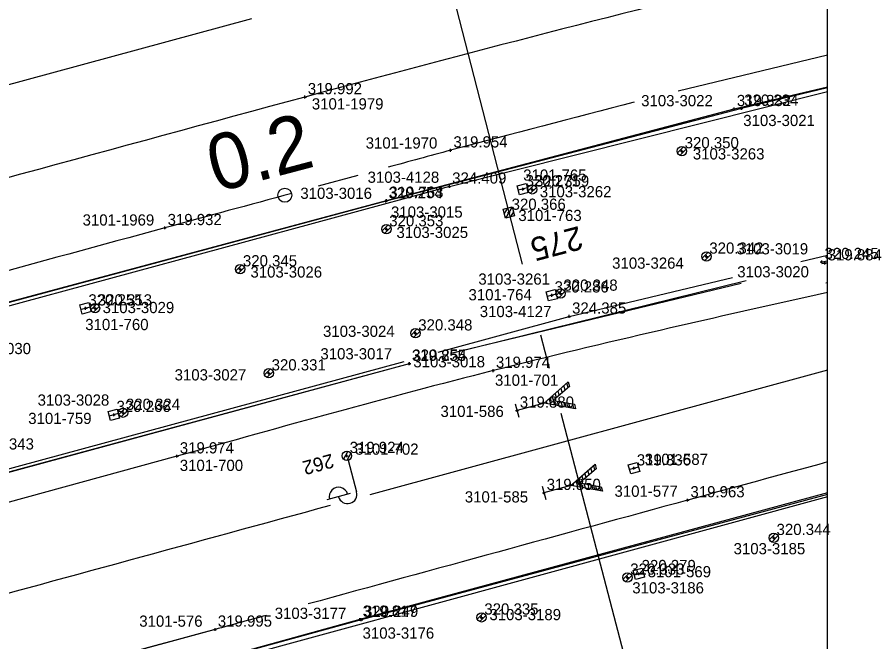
# Model space of a CAD drawing. Extents: x -821875 to -821475, y -1070280 to -1069975.
# Drawn here: x -821543.41 to -821497.95, y -1070194.92 to -1070161.48 of the extents above; entities that cross this region are included whole.
import ezdxf

# ---------------------------------------------------------------- set-up
doc = ezdxf.new("R2010")
doc.units = 0
for name, color, linetype in [('Vrstva 1', 7, 'Continuous'), ('Vrstva 11', 7, 'Continuous'), ('Vrstva 14', 7, 'Continuous'), ('Vrstva 25', 7, 'Continuous'), ('Vrstva 3', 7, 'Continuous'), ('Vrstva 36', 7, 'Continuous'), ('Vrstva 43', 7, 'Continuous'), ('Vrstva 6', 7, 'Continuous'), ('Vrstva 60', 7, 'Continuous'), ('Vrstva 61', 7, 'Continuous'), ('Vrstva 7', 7, 'Continuous')]:
    doc.layers.add(name, color=color, linetype=linetype)

# ---------------------------------------------------------------- blocks, each defined once
blk = doc.blocks.new('BOD')
at = {"layer": 'Vrstva 3'}
for p, q in [((-0.15, 0), (0.15, 0)), ((0, -0.15), (0, 0.15))]:
    blk.add_line(p, q, dxfattribs=at)

msp = doc.modelspace()

# ---------------------------------------------------------------- linework, layer by layer
at = {"layer": 'Vrstva 1'}
for p, q in [((-821530.858, -1070161.578), (-821554.553, -1070168.036)), ((-821500, -1070163.52), (-821508.002, -1070165.461)), ((-821525.155, -1070169.973), (-821527.289, -1070170.553)), ((-821500, -1070180.408), (-821524.524, -1070187.082)), ((-821532.805, -1070194.296), (-821551.797, -1070199.466))]:
    msp.add_line(p, q, dxfattribs=at)
msp.add_lwpolyline([(-821500, -1070000), (-821850, -1070000), (-821850, -1070250), (-821500, -1070250)], close=True, dxfattribs=at)
msp.add_lwpolyline([(-821500, -1070000), (-821850, -1070000), (-821850, -1070250), (-821500, -1070250)], close=True, dxfattribs=at)
msp.add_lwpolyline([(-821534.842, -1070185.015), (-821544.956, -1070187.779)], dxfattribs=at)
for points in [[(-821515.135, -1070116.801), (-821528.933, -1070119.148), (-821545.007, -1070122.191), (-821565.452, -1070126.847), (-821593.911, -1070134.524), (-821616.729, -1070140.773), (-821646.681, -1070148.977), (-821681.98, -1070158.691), (-821694.065, -1070162.076), (-821706.535, -1070165.88), (-821718.507, -1070169.937)], [(-821540.596, -1070125.428), (-821552.18, -1070128.307), (-821562.458, -1070130.974), (-821571.2, -1070133.262), (-821591.887, -1070138.848), (-821628.102, -1070148.713), (-821679.285, -1070162.663)], [(-821540.784, -1070127.42), (-821561.358, -1070134.748), (-821573.215, -1070138.464), (-821586.824, -1070142.326), (-821602.341, -1070146.553), (-821645.37, -1070158.257), (-821677.113, -1070166.912)], [(-821500, -1070129.211), (-821517.764, -1070133.43), (-821543.081, -1070140.233), (-821582.867, -1070151.05), (-821612.032, -1070158.997), (-821647.71, -1070168.745)], [(-821500, -1070134.157), (-821525.227, -1070140.424), (-821545.665, -1070145.962), (-821584.89, -1070156.649), (-821608.863, -1070163.173), (-821645.742, -1070173.228), (-821684.141, -1070183.689)], [(-821500, -1070139.002), (-821505.719, -1070140.359), (-821526.796, -1070145.75), (-821547.362, -1070151.333), (-821583.687, -1070161.245), (-821611.332, -1070168.765), (-821648.899, -1070179.006), (-821680.4, -1070187.609), (-821711.133, -1070195.974)], [(-821500, -1070143.947), (-821500.602, -1070144.082), (-821526.98, -1070150.62), (-821544.477, -1070155.432), (-821558.026, -1070159.151), (-821579.135, -1070164.951), (-821610.376, -1070173.463), (-821647.463, -1070183.595), (-821678.921, -1070192.191), (-821710.276, -1070200.761)], [(-821500, -1070148.817), (-821511.77, -1070151.622), (-821530.609, -1070156.564), (-821556.604, -1070163.701), (-821576.895, -1070169.217), (-821607.294, -1070177.525), (-821643.435, -1070187.343), (-821669.656, -1070194.488)], [(-821500, -1070158.612), (-821502.104, -1070159.113), (-821527.988, -1070165.772), (-821558.427, -1070174.094), (-821579.522, -1070179.891)], [(-821510.359, -1070166.051), (-821520.191, -1070168.624), (-821523.542, -1070169.535)], [(-821528.694, -1070170.935), (-821535.495, -1070172.784), (-821556.071, -1070178.381)], [(-821500, -1070176.236), (-821517.914, -1070180.43), (-821534.842, -1070185.015)], [(-821500, -1070185.322), (-821507.497, -1070187.368), (-821527.818, -1070192.932)], [(-821526.636, -1070187.658), (-821548.257, -1070193.56), (-821550.291, -1070194.116)], [(-821530.049, -1070193.542), (-821532.805, -1070194.296), (-821551.797, -1070199.466), (-821571.39, -1070204.838)]]:
    msp.add_spline(points, degree=3, dxfattribs=at)
at = {"layer": 'Vrstva 11'}
for p, q in [((-821528.453, -1070127.631), (-821517.074, -1070171.964)), ((-821517.15, -1070171.726), (-821517.319, -1070172.014)), ((-821516.896, -1070171.66), (-821517.251, -1070172.269)), ((-821517.074, -1070171.964), (-821516.355, -1070174.73)), ((-821516.828, -1070171.917), (-821516.995, -1070172.201)), ((-821515.371, -1070178.513), (-821514.907, -1070180.298)), ((-821514.279, -1070182.71), (-821510.391, -1070197.662))]:
    msp.add_line(p, q, dxfattribs=at)
msp.add_lwpolyline([(-821516.769, -1070172.142), (-821517.252, -1070172.269), (-821517.379, -1070171.786), (-821516.896, -1070171.659)], close=True, dxfattribs=at)
msp.add_lwpolyline([(-821516.769, -1070172.142), (-821517.252, -1070172.269), (-821517.379, -1070171.786), (-821516.896, -1070171.659), (-821516.769, -1070172.142)], dxfattribs=at)
at = {"layer": 'Vrstva 14'}
for p, q in [((-821520.255, -1070170.56), (-821500, -1070165.477)), ((-821520.255, -1070170.56), (-821573.139, -1070184.936)), ((-821501.435, -1070174.582), (-821500, -1070174.241)), ((-821513.835, -1070177.524), (-821505.089, -1070175.449)), ((-821520.849, -1070179.432), (-821513.835, -1070177.524)), ((-821550.394, -1070187.471), (-821522.684, -1070179.932)), ((-821500, -1070187.198), (-821569.776, -1070206.214))]:
    msp.add_line(p, q, dxfattribs=at)
for points in [[(-821523.624, -1070171.317), (-821505.012, -1070166.408), (-821500, -1070165.22)], [(-821500, -1070165.281), (-821504.618, -1070166.388), (-821523.662, -1070171.348)], [(-821553.163, -1070179.239), (-821523.624, -1070171.317)], [(-821523.662, -1070171.348), (-821552.814, -1070179.193)], [(-821500.361, -1070174.612), (-821500.318, -1070174.601)], [(-821500.318, -1070174.601), (-821500, -1070174.544)], [(-821500.15, -1070174.674), (-821500.305, -1070174.711)], [(-821500, -1070174.647), (-821500.15, -1070174.674)], [(-821520.078, -1070179.475), (-821504.369, -1070175.6)], [(-821504.632, -1070175.758), (-821520.105, -1070179.502)], [(-821550.335, -1070187.597), (-821522.393, -1070180.046)], [(-821522.413, -1070180.061), (-821550.25, -1070187.611)], [(-821500, -1070186.984), (-821525.05, -1070193.765)], [(-821500, -1070187.066), (-821524.974, -1070193.772)], [(-821524.974, -1070193.772), (-821568.963, -1070205.855)], [(-821525.05, -1070193.765), (-821568.859, -1070205.873)]]:
    msp.add_lwpolyline(points, dxfattribs=at)
at = {"layer": 'Vrstva 25'}
for p, q in [((-821525.688, -1070184.75), (-821525.926, -1070185.165)), ((-821525.534, -1070184.859), (-821525.753, -1070185.241)), ((-821525.68, -1070185.234), (-821525.223, -1070186.923)), ((-821525.56, -1070187.014), (-821526.816, -1070187.354))]:
    msp.add_line(p, q, dxfattribs=at)
msp.add_circle((-821525.746, -1070184.992), 0.25, dxfattribs=at)
msp.add_circle((-821525.746, -1070184.992), 0.25, dxfattribs=at)
for centre, start, end in [((-821526.19, -1070187.178), 14.4585, 195.8637), ((-821525.706, -1070187.053), 195.1611, 15.1611)]:
    msp.add_arc(centre, 0.5, start, end, dxfattribs=at)
at = {"layer": 'Vrstva 3'}
msp.add_line((-821500, -1070175.725), (-821500.092, -1070175.744), dxfattribs=at)
at = {"layer": 'Vrstva 36'}
for p, q in [((-821508.036, -1070168.759), (-821507.714, -1070168.436)), ((-821507.906, -1070168.894), (-821507.579, -1070168.566)), ((-821516.052, -1070170.81), (-821515.728, -1070170.487)), ((-821515.922, -1070170.945), (-821515.594, -1070170.618)), ((-821523.856, -1070172.939), (-821523.534, -1070172.616)), ((-821523.726, -1070173.074), (-821523.399, -1070172.746)), ((-821506.718, -1070174.405), (-821506.394, -1070174.082)), ((-821506.588, -1070174.54), (-821506.26, -1070174.212)), ((-821531.692, -1070175.086), (-821531.37, -1070174.763)), ((-821531.562, -1070175.221), (-821531.235, -1070174.894)), ((-821514.528, -1070176.391), (-821514.204, -1070176.068)), ((-821514.398, -1070176.526), (-821514.07, -1070176.198)), ((-821539.462, -1070177.181), (-821539.14, -1070176.858)), ((-821539.332, -1070177.316), (-821539.005, -1070176.988)), ((-821522.304, -1070178.521), (-821521.982, -1070178.198)), ((-821522.174, -1070178.656), (-821521.847, -1070178.328)), ((-821530.156, -1070180.661), (-821529.832, -1070180.338)), ((-821530.026, -1070180.796), (-821529.698, -1070180.468)), ((-821537.958, -1070182.774), (-821537.634, -1070182.451)), ((-821537.828, -1070182.909), (-821537.5, -1070182.582)), ((-821503.116, -1070189.478), (-821502.794, -1070189.155)), ((-821502.986, -1070189.613), (-821502.659, -1070189.286)), ((-821510.952, -1070191.603), (-821510.628, -1070191.28)), ((-821510.822, -1070191.738), (-821510.494, -1070191.41)), ((-821518.764, -1070193.74), (-821518.442, -1070193.417)), ((-821518.634, -1070193.875), (-821518.307, -1070193.548))]:
    msp.add_line(p, q, dxfattribs=at)
for centre in [(-821507.806, -1070168.667), (-821515.821, -1070170.718), (-821523.626, -1070172.847), (-821506.487, -1070174.313), (-821531.462, -1070174.994), (-821514.297, -1070176.299), (-821539.232, -1070177.089), (-821522.074, -1070178.429), (-821529.925, -1070180.569), (-821537.727, -1070182.682), (-821502.886, -1070189.386), (-821510.721, -1070191.511), (-821518.534, -1070193.648)]:
    msp.add_circle(centre, 0.25, dxfattribs=at)
at = {"layer": 'Vrstva 43'}
for points in [[(-821516.081, -1070170.639), (-821516.017, -1070170.881), (-821516.501, -1070171.009), (-821516.629, -1070170.525), (-821516.145, -1070170.397), (-821516.081, -1070170.639), (-821516.565, -1070170.767)], [(-821514.529, -1070176.332), (-821514.468, -1070176.575), (-821514.954, -1070176.697), (-821515.076, -1070176.211), (-821514.59, -1070176.089), (-821514.529, -1070176.332), (-821515.015, -1070176.454)], [(-821539.494, -1070177.023), (-821539.429, -1070177.265), (-821539.912, -1070177.396), (-821540.043, -1070176.913), (-821539.56, -1070176.782), (-821539.494, -1070177.023), (-821539.978, -1070177.155)], [(-821537.988, -1070182.731), (-821537.923, -1070182.972), (-821538.405, -1070183.102), (-821538.535, -1070182.62), (-821538.053, -1070182.49), (-821537.988, -1070182.731), (-821538.47, -1070182.861)], [(-821510.129, -1070185.594), (-821510.063, -1070185.835), (-821510.545, -1070185.967), (-821510.677, -1070185.485), (-821510.195, -1070185.353), (-821510.129, -1070185.594), (-821510.611, -1070185.726)], [(-821509.87, -1070191.255), (-821509.804, -1070191.496), (-821510.286, -1070191.628), (-821510.418, -1070191.146), (-821509.936, -1070191.014), (-821509.87, -1070191.255), (-821510.352, -1070191.387)]]:
    msp.add_lwpolyline(points, dxfattribs=at)
at = {"layer": 'Vrstva 6'}
for p, q in [((-821513.898, -1070181.333), (-821513.964, -1070181.093)), ((-821514.369, -1070181.741), (-821514.434, -1070181.505)), ((-821514.212, -1070181.605), (-821514.278, -1070181.368)), ((-821514.055, -1070181.469), (-821514.121, -1070181.23)), ((-821515.021, -1070182.196), (-821515.06, -1070182.055)), ((-821514.816, -1070182.234), (-821514.904, -1070181.917)), ((-821514.683, -1070182.013), (-821514.747, -1070181.78)), ((-821514.612, -1070182.271), (-821514.676, -1070182.038)), ((-821514.526, -1070181.877), (-821514.591, -1070181.643)), ((-821515.187, -1070182.166), (-821516.633, -1070182.565)), ((-821515.172, -1070182.169), (-821515.175, -1070182.155)), ((-821514.407, -1070182.309), (-821514.472, -1070182.074)), ((-821514.202, -1070182.346), (-821514.267, -1070182.11)), ((-821513.997, -1070182.384), (-821514.063, -1070182.146)), ((-821513.792, -1070182.422), (-821513.858, -1070182.183)), ((-821513.587, -1070182.459), (-821513.653, -1070182.219)), ((-821512.618, -1070185.88), (-821512.684, -1070185.641)), ((-821512.461, -1070185.744), (-821512.527, -1070185.504)), ((-821513.089, -1070186.288), (-821513.154, -1070186.053)), ((-821512.932, -1070186.152), (-821512.997, -1070185.916)), ((-821512.775, -1070186.016), (-821512.841, -1070185.779)), ((-821513.751, -1070186.576), (-821515.197, -1070186.974)), ((-821513.735, -1070186.579), (-821513.739, -1070186.565)), ((-821513.585, -1070186.607), (-821513.624, -1070186.465)), ((-821513.38, -1070186.644), (-821513.467, -1070186.327)), ((-821513.246, -1070186.424), (-821513.311, -1070186.19)), ((-821513.175, -1070186.682), (-821513.24, -1070186.449)), ((-821512.97, -1070186.719), (-821513.035, -1070186.485)), ((-821512.766, -1070186.757), (-821512.831, -1070186.521)), ((-821512.561, -1070186.795), (-821512.626, -1070186.557)), ((-821512.356, -1070186.833), (-821512.422, -1070186.594)), ((-821512.151, -1070186.87), (-821512.217, -1070186.63))]:
    msp.add_line(p, q, dxfattribs=at)
for points in [[(-821515.187, -1070182.166), (-821513.893, -1070181.03), (-821513.826, -1070181.271), (-821514.705, -1070182.033), (-821513.56, -1070182.235), (-821513.494, -1070182.476), (-821515.187, -1070182.166)], [(-821515.187, -1070182.166), (-821513.893, -1070181.03), (-821513.826, -1070181.271), (-821514.705, -1070182.033), (-821513.56, -1070182.235), (-821513.494, -1070182.476), (-821515.187, -1070182.166)], [(-821516.733, -1070182.204), (-821516.533, -1070182.926)], [(-821513.751, -1070186.576), (-821512.456, -1070185.441), (-821512.389, -1070185.682), (-821513.269, -1070186.443), (-821512.124, -1070186.647), (-821512.058, -1070186.888), (-821513.751, -1070186.576)], [(-821513.751, -1070186.576), (-821512.456, -1070185.441), (-821512.389, -1070185.682), (-821513.269, -1070186.443), (-821512.124, -1070186.647), (-821512.058, -1070186.888), (-821513.751, -1070186.576)], [(-821515.296, -1070186.613), (-821515.098, -1070187.335)]]:
    msp.add_lwpolyline(points, dxfattribs=at)
at = {"layer": 'Vrstva 7'}
msp.add_circle((-821529.065, -1070171.034), 0.375, dxfattribs=at)

# ---------------------------------------------------------------- block references
at = {"layer": 'Vrstva 60', "xscale": 0.5, "yscale": 0.5}
for p in [(-821527.988, -1070165.772), (-821505.012, -1070166.408), (-821504.618, -1070166.388), (-821520.191, -1070168.624), (-821507.806, -1070168.667), (-821520.255, -1070170.56), (-821516.323, -1070170.703), (-821515.821, -1070170.718), (-821523.662, -1070171.348), (-821523.624, -1070171.317), (-821517.074, -1070171.964), (-821535.495, -1070172.784), (-821523.626, -1070172.847), (-821506.487, -1070174.313), (-821500.318, -1070174.601), (-821500.15, -1070174.674), (-821531.462, -1070174.994), (-821514.772, -1070176.393), (-821514.297, -1070176.299), (-821539.736, -1070177.089), (-821539.232, -1070177.089), (-821513.835, -1070177.524), (-821522.074, -1070178.429), (-821522.413, -1070180.061), (-821522.393, -1070180.046), (-821529.925, -1070180.569), (-821517.914, -1070180.43), (-821516.633, -1070182.565), (-821538.229, -1070182.796), (-821537.727, -1070182.682), (-821534.842, -1070185.015), (-821525.746, -1070184.992), (-821510.37, -1070185.66), (-821515.197, -1070186.974), (-821507.497, -1070187.368), (-821502.886, -1070189.386), (-821510.721, -1070191.511), (-821510.111, -1070191.321), (-821525.05, -1070193.765), (-821524.974, -1070193.772), (-821518.534, -1070193.648), (-821532.805, -1070194.296)]:
    msp.add_blockref('BOD', p, dxfattribs=at)

# ---------------------------------------------------------------- texts
at = {"layer": 'Vrstva 11'}
msp.add_text('275', height=1.25, rotation=194.708, dxfattribs=at).set_placement((-821513.316, -1070172.672))
at = {"layer": 'Vrstva 25'}
msp.add_text('262', height=0.75, rotation=195.1611, dxfattribs=at).set_placement((-821526.563, -1070184.871))
at = {"layer": 'Vrstva 60'}
for s, p in [('3103-3022', (-821509.986, -1070166.266)), ('3101-1979', (-821527.621, -1070166.438)), ('3103-3021', (-821504.52, -1070167.326)), ('3101-1970', (-821524.738, -1070168.533)), ('3103-3263', (-821507.219, -1070169.117)), ('3103-4128', (-821524.637, -1070170.367)), ('3101-765', (-821516.302, -1070170.252)), ('3103-3016', (-821528.238, -1070171.227)), ('3103-3262', (-821515.414, -1070171.142)), ('3101-1969', (-821539.897, -1070172.657)), ('3103-3015', (-821523.383, -1070172.235)), ('3101-763', (-821516.564, -1070172.414)), ('3103-3025', (-821523.09, -1070173.323)), ('3103-3019', (-821504.881, -1070174.202)), ('3103-3264', (-821511.539, -1070174.969)), ('3103-3026', (-821530.909, -1070175.444)), ('3103-3261', (-821518.705, -1070175.823)), ('3103-3020', (-821504.841, -1070175.433)), ('3101-764', (-821519.232, -1070176.663)), ('3103-3029', (-821538.827, -1070177.348)), ('3103-4127', (-821518.63, -1070177.563)), ('3101-760', (-821539.756, -1070178.259)), ('3103-3024', (-821527.023, -1070178.622)), ('3103-3030', (-821546.497, -1070179.546)), ('3103-3017', (-821527.161, -1070179.827)), ('3103-3018', (-821522.186, -1070180.254)), ('3103-3027', (-821534.97, -1070180.955)), ('3101-701', (-821517.815, -1070181.24)), ('3103-3028', (-821542.306, -1070182.306)), ('3101-586', (-821520.732, -1070182.912)), ('3101-759', (-821542.808, -1070183.289)), ('3101-702', (-821525.299, -1070184.934)), ('3101-700', (-821534.692, -1070185.804)), ('3101-587', (-821509.8, -1070185.48)), ('3101-577', (-821511.414, -1070187.188)), ('3101-585', (-821519.43, -1070187.494)), ('3103-3185', (-821505.037, -1070190.269)), ('3101-569', (-821509.636, -1070191.501)), ('3103-3186', (-821510.462, -1070192.366)), ('3103-3177', (-821529.61, -1070193.729)), ('3103-3189', (-821518.113, -1070193.8)), ('3101-576', (-821536.863, -1070194.15)), ('3103-3176', (-821524.905, -1070194.79))]:
    msp.add_text(s, height=0.6, dxfattribs=at).set_placement(p)
at = {"layer": 'Vrstva 61'}
for s, p in [('319.992', (-821527.838, -1070165.622)), ('319.832', (-821504.862, -1070166.258)), ('320.234', (-821504.468, -1070166.238)), ('319.954', (-821520.041, -1070168.474)), ('320.350', (-821507.656, -1070168.517)), ('324.409', (-821520.105, -1070170.41)), ('320.271', (-821516.173, -1070170.553)), ('320.359', (-821515.671, -1070170.568)), ('320.254', (-821523.512, -1070171.198)), ('319.763', (-821523.474, -1070171.167)), ('320.366', (-821516.924, -1070171.814)), ('319.932', (-821535.345, -1070172.634)), ('320.353', (-821523.476, -1070172.697)), ('320.342', (-821506.337, -1070174.163)), ('320.245', (-821500.168, -1070174.451)), ('320.345', (-821531.312, -1070174.844)), ('319.884', (-821500, -1070174.524)), ('320.286', (-821514.622, -1070176.243)), ('320.348', (-821514.147, -1070176.149)), ('320.255', (-821539.586, -1070176.939)), ('320.313', (-821539.082, -1070176.939)), ('324.385', (-821513.685, -1070177.374)), ('320.348', (-821521.924, -1070178.279)), ('319.855', (-821522.263, -1070179.911)), ('320.254', (-821522.243, -1070179.896)), ('319.974', (-821517.764, -1070180.28)), ('320.331', (-821529.775, -1070180.419)), ('320.266', (-821538.079, -1070182.646)), ('320.324', (-821537.577, -1070182.532)), ('319.880', (-821516.483, -1070182.415)), ('320.343', (-821545.404, -1070184.657)), ('319.974', (-821534.692, -1070184.865)), ('319.924', (-821525.596, -1070184.842)), ('319.836', (-821510.22, -1070185.51)), ('319.850', (-821515.047, -1070186.824)), ('319.963', (-821507.347, -1070187.218)), ('320.344', (-821502.736, -1070189.236)), ('320.279', (-821509.961, -1070191.171)), ('320.333', (-821510.571, -1070191.361)), ('320.335', (-821518.384, -1070193.498)), ('319.817', (-821524.9, -1070193.615)), ('320.249', (-821524.824, -1070193.622)), ('319.995', (-821532.655, -1070194.146))]:
    msp.add_text(s, height=0.6, dxfattribs=at).set_placement(p)
at = {"layer": 'Vrstva 7'}
msp.add_text('0.2', height=3, rotation=14.82, dxfattribs=at).set_placement((-821532.75, -1070170.893))

doc.saveas('drawing.dxf')
